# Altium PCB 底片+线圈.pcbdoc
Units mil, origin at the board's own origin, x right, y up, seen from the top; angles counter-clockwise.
Board outline 3346.45 x 2125.98 mil, 2 copper layers (Top Layer, Bottom Layer); 0 components, 3 nets, 2 pads, 2 vias.
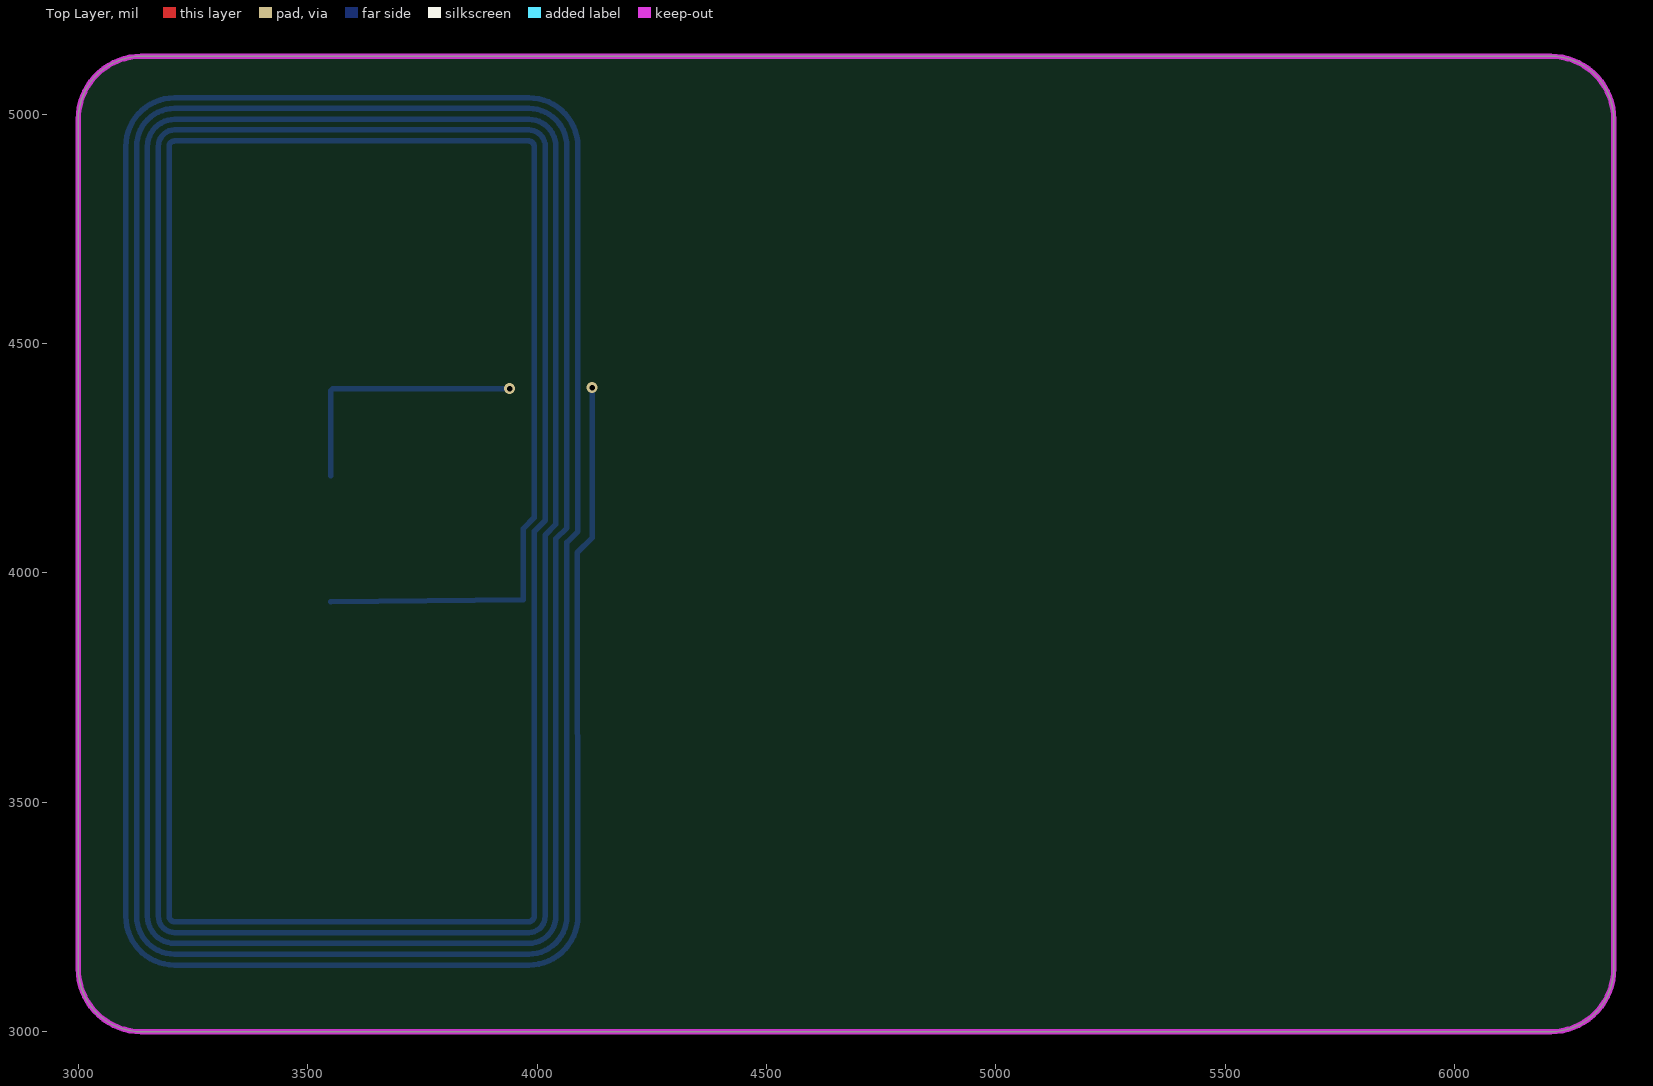
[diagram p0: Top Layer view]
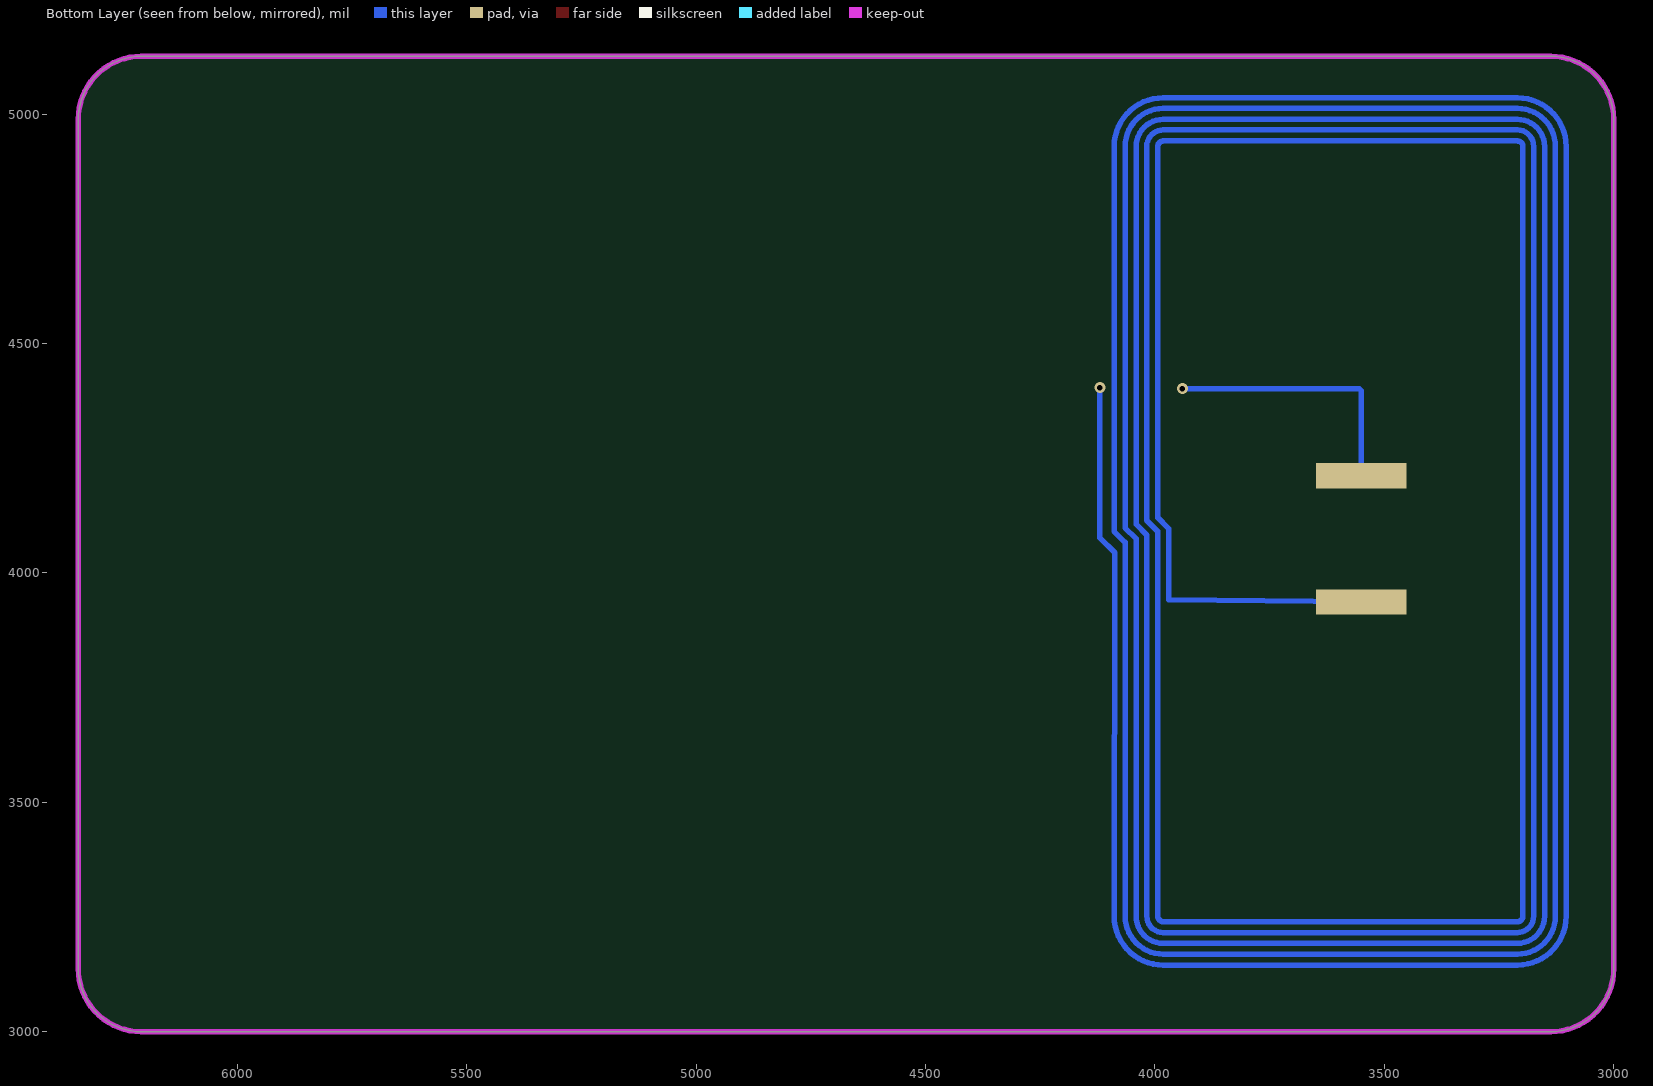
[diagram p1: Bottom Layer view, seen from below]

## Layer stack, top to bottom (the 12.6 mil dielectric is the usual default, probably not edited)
Top Layer: signal copper (thickness not stored)
Dielectric: dielectric 12.6, FR-4, Dk 4.8
Bottom Layer: signal copper (thickness not stored)

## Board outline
6208.65,5125.98 cw(c6208.65,4988.19) 6346.45,4988.19 6346.45,3137.8 cw(c6208.65,3137.8) 6208.65,3000 3137.8,3000 cw(c3137.8,3137.8) 3000,3137.8 3000,4988.19 cw(c3137.8,4988.19) 3137.8,5125.98

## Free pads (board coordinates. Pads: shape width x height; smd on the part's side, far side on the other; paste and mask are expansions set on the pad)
  rect 196.85x55.12 smd far side paste+0 mask-196.85: 11(3550,3936.69) 11(3550,4211.69)

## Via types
v1: diameter 24, hole 12, Top Layer to Bottom Layer, 2 vias

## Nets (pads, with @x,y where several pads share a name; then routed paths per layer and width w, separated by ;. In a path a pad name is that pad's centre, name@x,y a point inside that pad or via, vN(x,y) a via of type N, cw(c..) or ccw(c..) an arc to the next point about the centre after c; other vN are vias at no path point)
S$48780: pad.11@3550,3936.69 | length 1417.4
  Bottom Layer w12: pad.11@3550,3936.69 3970,3941.69 3970,4096.69 3993.8,4120.49 3993.8,4929.19
S$48796: pad.11@3550,4211.69 | length 26457.8
  Bottom Layer w12: 3103.7,4929.27 cw(c3209.85,4929.13) 3210,5035.27 ; 3103.7,4929.27 3103.7,3251.69 ccw(c3210,3251.69) 3210,3145.39 3981.83,3145.39 ccw(c3982.18,3252.04) 4088.83,3251.69 4087.44,4043.95 ; 3127.32,4929.27 cw(c3210.16,4929.44) 3210,5012.27 ; 3127.32,4929.27 3127.32,3251.69 ccw(c3210,3251.69) 3210,3169.02 3981.83,3169.02 ccw(c3981.99,3251.85) 4064.83,3251.69 4064.83,4066.65 4088.83,4090.28 4088.83,4929.27 ccw(c3982.33,4928.77) 3981.83,5035.28 3210,5035.28 ; 3174.57,4929.27 cw(c3210.28,4929.56) 3210,4965.27 ; 3174.57,4929.27 3174.57,3251.69 ccw(c3210,3251.69) 3210,3216.26 3981.83,3216.26 ccw(c3982.11,3251.98) 4017.83,3251.69 4017.83,4082.4 4040.83,4106.28 4040.83,4929.27 ccw(c3981.83,4929.27) 3981.83,4988.27 3210,4988.28 ; 3210,4965.28 3981.83,4965.28 cw(c3981.83,4929.27) 4017.83,4929.27 4017.83,4114.27 3993.83,4090.28 3993.83,3251.69 cw(c3981.92,3251.79) 3981.83,3239.88 3210,3239.88 cw(c3210,3251.69) 3198.19,3251.69 3198.19,4929.27 cw(c3210.09,4929.37) 3210,4941.28 3981.83,4941.28 cw(c3981.83,4929.27) 3993.83,4929.27 ; 3210,4988.27 ccw(c3209.97,4929.25) 3150.95,4929.28 3150.95,3251.69 ccw(c3210,3251.69) 3210,3192.64 3981.83,3192.64 ccw(c3981.8,3251.66) 4040.83,3251.69 4040.83,4074.53 4064.83,4098.28 4064.83,4929.27 ccw(c3981.83,4929.27) 3981.83,5012.27 3210,5012.27
  Bottom Layer w12.01: pad.11@3550,4211.69 3550,4396.69 3555,4401.69 v1(3940,4401.69) ; 4087.45,4043.93 4120,4076.47 v1(4120,4403.98)
"": 

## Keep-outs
Board Outline Layer:
  the board outline again, w11.81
